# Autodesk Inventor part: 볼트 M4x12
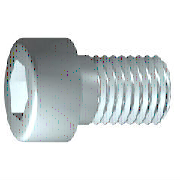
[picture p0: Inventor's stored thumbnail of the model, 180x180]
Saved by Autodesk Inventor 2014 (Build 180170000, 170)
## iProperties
IsCustomPart: 0
Created: 2012-02
Part Number: 볼트 M4x12
Material: 강철, 연강
Description: 6각머리 태핑 나사
Document SubType Name: Modeling
Standard: KS B 1003
Designer: mduedu
Standards Organization: KS
Language: ko-KR
Size Designation: M 4 x 12
Categories: <MemberInstance><Categories><Category DisplayName="조임쇠" InternalName="e4da775c-781d-43d5-af7c-5136215cf5a6" Mnemonic="FSTN"><Category DisplayName="볼트" InternalN
Density: 1 g/cm^3
Appearance: Steel
Author: mduedu
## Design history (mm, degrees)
sketch "스케치1"
  geometry: L1 (-1, 0)-(12, 0); L2 (12, 0)-(12, 2); L3 (12, 2)-(1.75, 2); L4 (1.75, 2)-(1.32, 2); L5 (1.32, 2)-(0, 2); L6 (0, 2)-(0, 3.5); L7 (0, 3.5)-(-4, 3.5); L8 (-4, 3.5)-(-4, 1.732); L9 (-4, 1.732)-(-2, 1.732); L10 (-2, 1.732)-(-1, 0); L11 (-7.2, 0)-(15.2, 0) reference; L12 (0, -0.7)-(0, 4.2) reference; L13 (1.75, 2)-(0, 2)
  constraints: 22 end point, 6 parallel, 2 collinear, 2 perpendicular, 1 horizontal, 1 point on line
  dimensions: "d1" = 10.25 distance from line of L3.end L2 (= GEL); "d2" = 0.42952 distance of L4.end L3.end (computed from GAL); "d3" = 4 distance between parallel lines of L8 L6 (= KOH); "d4" = 2 distance of L8.end L9.end (= INTI); "d5" = 60 deg angle of L10 L1; "d6" = 4 diameter of L3 L1 (= GD); "d7" = 4 diameter of L5 L1 (= BDM); "d8" = 3.4641 diameter of L9 L1 (= 1.1547 x SW); "d9" = 7 diameter of L7 L1 (= KOD); "d26" = 12 distance between parallel lines of L12 L2 (= NLG)
revolve "본체" sketch "스케치1" stored, may be unused: angle "d10" = 90 deg
sketch "스케치2"
  geometry: L1 (0, -4.9)-(0, 4.9) reference; L2 (-4.9, 0)-(4.9, 0) reference; L3 (1.732, 0)-(0.866, -1.5); L4 (0.866, -1.5)-(-0.866, -1.5); L5 (-0.866, -1.5)-(-1.732, 0); L6 (-1.732, 0)-(-0.866, 1.5); L7 (-0.866, 1.5)-(0.866, 1.5); L8 (0.866, 1.5)-(1.732, 0); 2 further points
  constraints: 12 end point, 1 coincident, 1 horizontal alignment, 1 point on line, 12 other
extrude "슬롯" join sketch "스케치2" stored distance "d11" = 10; taper "d12" = 0 deg
workplane "Work Plane1"
fillet "Fillet2" dims "d30" = 0.1 (= R)
body "Solid1"
fillet "모깎기1" dims "d17" = 0.4 (= RR)
feature "스레드" dims "d13" = 10.25 (= GEL), "d14" = 0
chamfer "모따기1" distance "d15" = 0.42941 (= -0.5 x SPD + 0.5 x GD); stored, may be unused: second distance "d16" = 0.42941 (= GUL), angle "d27" = 45 deg
other parameters: "GD" = 4 (= NND) [user parameter; used in 2 equation terms], "NLG" = 12 [user parameter; used in 1 equation term], "GEL" = 10.25 [user parameter; used in 2 equation terms], "KOD" = 7 [user parameter; used in 1 equation term], "KOH" = 4 [user parameter; used in 1 equation term], "INTI" = 2 [user parameter; used in 1 equation term], "GAL" = 0.42941 (= 0.61345 x PTC) [user parameter; used in 1 equation term], "GUL" = 0.42941 (= 0.61345 x PTC) [user parameter; used in 1 equation term], "BDM" = 4 (= NND) [user parameter; used in 1 equation term], "SW" = 3 [user parameter; used in 2 equation terms], "RR" = 0.4 [user parameter; used in 1 equation term], "SPD" = 3.14117 (= NND - 1.2269 x PTC) [user parameter; used in 1 equation term], "d19" = 0, "d28" = 0, "d29" = 0, "R" = 0.1 [user parameter; used in 1 equation term], "PHH" = 0.2 [user parameter], "GD1" = 3.14117 (= THREADDIA - 1.2269 x PTC) [user parameter], "THREADDIA" = 4 [user parameter; used in 1 equation term], "FAWI" = 45 deg [user parameter], "TPU" = 14.28571 (computed from PTC) [user parameter], "PTC" = 0.7 [user parameter; used in 5 equation terms], "NND" = 4 [user parameter; used in 3 equation terms], "TOA" = 30 deg [user parameter], "E0" = 3.465 (= 1.155 x SW) [user parameter]
